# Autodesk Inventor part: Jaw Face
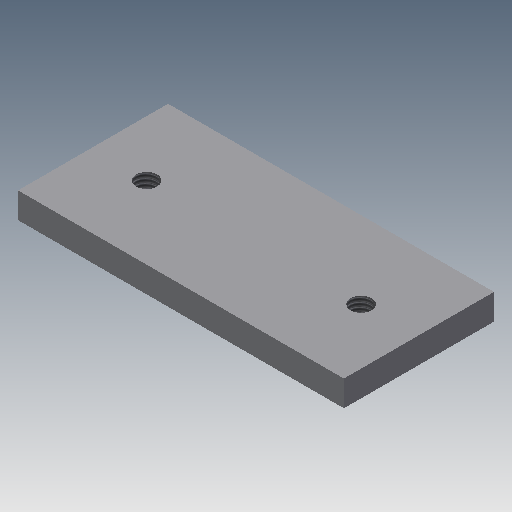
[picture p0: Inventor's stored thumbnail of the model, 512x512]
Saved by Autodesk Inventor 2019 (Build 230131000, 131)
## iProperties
Shininess: 77.0
Length Units: 11269
Angle Units: 11279
Time Units: 11290
Mass Units: 11283
Length Display Precision: 3
Angle Display Precision: 2
Compacted: True
Created: 2002-02
Part Number: Jaw Face
Document SubType Name: Modeling
Designer: ***
Density: 1 g/cm^3
Material: Generic
Mass: 15.6207 g
Surface Area: 67.651 cm^2
Volume: 15.6207 cm^3
Appearance: Default
Density: 0.0
Volumn: 0.0
Area: 0.0
PropertySet Name: Model Information
Control State: 0
Master: False
Checked Out: False
Author: ***
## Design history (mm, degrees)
sketch "Sketch1"
  geometry: L1 (-79.661, -8.43)-(-3.661, -8.43); L2 (-3.661, -8.43)-(-3.661, -43.43); L3 (-3.661, -43.43)-(-79.661, -43.43); L4 (-79.661, -43.43)-(-79.661, -8.43)
  constraints: 8 end point, 2 parallel, 1 horizontal, 1 perpendicular
  dimensions: "d0" = 76 distance of L2.end L3.end; "d3" = 35 distance of L1.end L2.end
extrude "Extrusion1" new body sketch "Sketch1" stored distance "d7" = 6; taper "d8" = 0 deg
hole "Hole1" diameter "d11" = 4.917; stored, may be unused: countersink angle "d15" = 90 deg, drill point angle "d17" = 118 deg; dims "d9" = 13, "d10" = 18, "d12" = 12, "d13" = 4, "d14" = 2, "d16" = 17.1
pattern_linear "Rectangular Pattern1" dims "d20" = -50
body "Solid1"
